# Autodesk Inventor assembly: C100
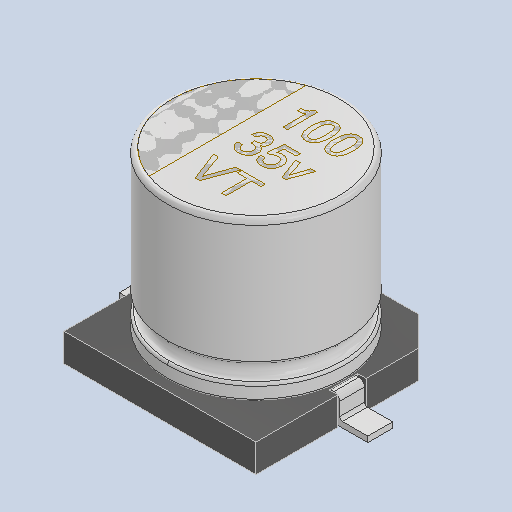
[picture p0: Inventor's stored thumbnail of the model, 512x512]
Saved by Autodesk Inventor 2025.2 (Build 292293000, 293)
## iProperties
Created: 2025-04
Part Number: C100
Description: PART--DESC
Document SubType Name: Assembly
Designer: BennF
Author: BennF
Revision Number: NONE
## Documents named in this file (4)
- C:\Users\BennF\Nextcloud\Benutzer\CNC JarBeRi\existing parts\Electronics\RepRap A4988 Shied (USE WITHOUT ARDUINO)\reprap-a4988-1.snapshot.1\RepRap\RepRap\C100_4.iam
- C:\Users\BennF\Nextcloud\Benutzer\CNC JarBeRi\existing parts\Electronics\RepRap A4988 Shied (USE WITHOUT ARDUINO)\reprap-a4988-1.snapshot.1\RepRap\RepRap\C100 Geometry.ipt
- C:\Users\BennF\Nextcloud\Benutzer\CNC JarBeRi\existing parts\Electronics\RepRap A4988 Shied (USE WITHOUT ARDUINO)\reprap-a4988-1.snapshot.1\RepRap\RepRap\name3.ipt
- C:\Users\BennF\Nextcloud\Benutzer\CNC JarBeRi\existing parts\Electronics\RepRap A4988 Shied (USE WITHOUT ARDUINO)\reprap-a4988-1.snapshot.1\RepRap\RepRap\bay_4.iam
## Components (3 placed, 3 different names)
1. C100 Geometry
2. name3
3. bay [sub-assembly]
